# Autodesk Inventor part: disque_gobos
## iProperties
Created: 2011-01
Part Number: disque_gobos
Document SubType Name: Modeling
Designer: eric
Density: 1 g/cm^3
Mass: 6.58458 g
Surface Area: 155.709 cm^2
Volume: 6.58458 cm^3
Author: eric
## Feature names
1. Base1
